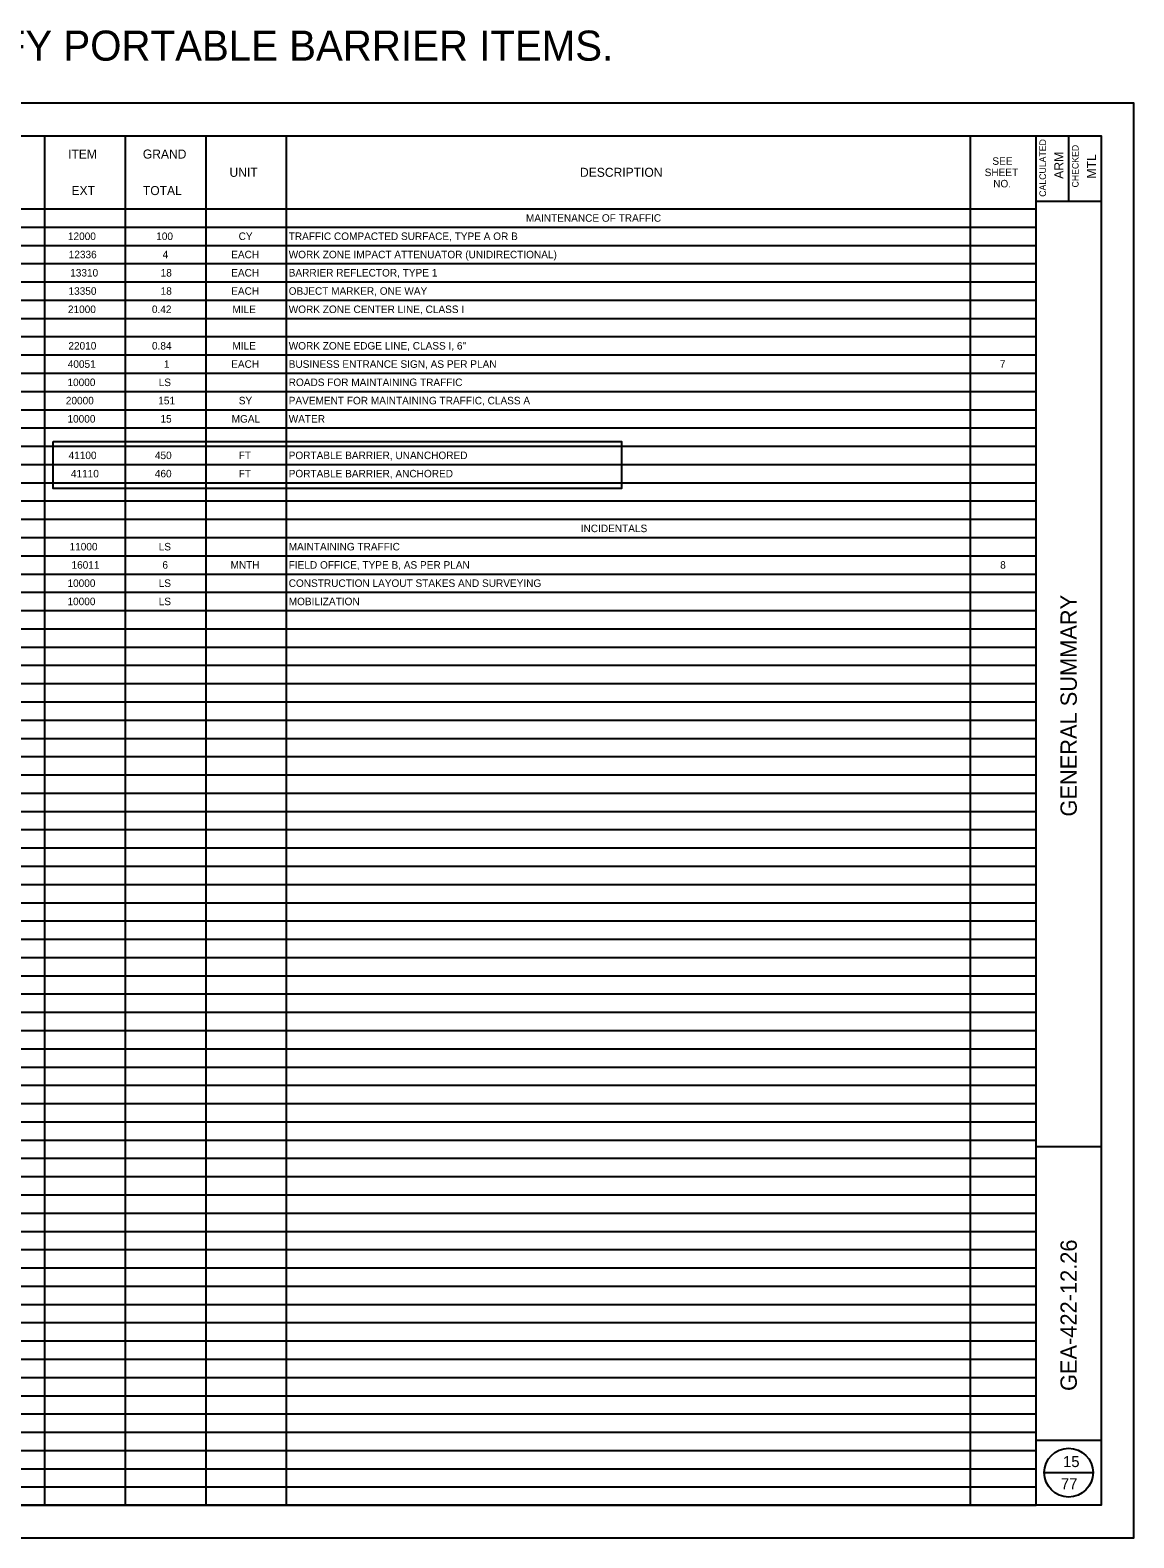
# Model space of a CAD drawing. Extents: x 0 to 34, y 0 to 23.1.
# Drawn here: x 17.07 to 34, y 0 to 23.12 of the extents above; entities that cross this region are included whole.
import ezdxf

# ---------------------------------------------------------------- set-up
doc = ezdxf.new("R2010")
doc.units = 0
for name, color, linetype in [('SC_Scratch1', 7, 'Continuous'), ('SH_Border', 7, 'Continuous'), ('SH_Cut_Line', 7, 'Continuous'), ('SH_Data', 7, 'Continuous'), ('SH_Text', 7, 'Continuous')]:
    doc.layers.add(name, color=color, linetype=linetype)

msp = doc.modelspace()

# ---------------------------------------------------------------- linework, layer by layer
at = {"layer": 'SC_Scratch1'}
msp.add_lwpolyline([(17.425, 16.812), (26.141, 16.812), (26.141, 16.091), (17.425, 16.091)], close=True, dxfattribs=at)
at = {"layer": 'SH_Border'}
for p, q in [((32.5, 0.5), (32.5, 21.5)), ((33, 21.5), (33, 20.5)), ((32.5, 20.5), (33.5, 20.5)), ((32.5, 6), (33.5, 6)), ((32.5, 1.5), (33.5, 1.5))]:
    msp.add_line(p, q, dxfattribs=at)
msp.add_lwpolyline([(2, 21.5), (33.5, 21.5), (33.5, 0.5), (2, 0.5)], close=True, dxfattribs=at)
at = {"layer": 'SH_Cut_Line'}
msp.add_lwpolyline([(0, 0), (34, 0), (34, 22), (0, 22)], close=True, dxfattribs=at)
at = {"layer": 'SH_Data'}
msp.add_line((32.625, 1), (33.375, 1), dxfattribs=at)
msp.add_circle((33, 1), 0.375, dxfattribs=at)
at = {"layer": 'SH_Text'}
for p, q in [((2, 21.5), (32.5, 21.5)), ((17.299, 0.5), (17.299, 21.5)), ((18.535, 0.5), (18.535, 21.5)), ((19.77, 0.5), (19.77, 21.5)), ((21.005, 0.5), (21.005, 21.5)), ((31.495, 0.5), (31.495, 21.5)), ((32.5, 0.5), (32.5, 21.5)), ((14.055, 20.38), (32.5, 20.38)), ((19.77, 20.38), (32.5, 20.38)), ((2, 20.1), (32.5, 20.1)), ((2, 19.82), (32.5, 19.82)), ((2, 19.54), (32.5, 19.54)), ((2, 19.26), (32.5, 19.26)), ((2, 18.98), (32.5, 18.98)), ((2, 18.7), (32.5, 18.7)), ((2, 18.42), (32.5, 18.42)), ((2, 18.14), (32.5, 18.14)), ((2, 17.86), (32.5, 17.86)), ((2, 17.58), (32.5, 17.58)), ((2, 17.3), (32.5, 17.3)), ((2, 17.02), (32.5, 17.02)), ((2, 16.74), (32.5, 16.74)), ((2, 16.46), (32.5, 16.46)), ((2, 16.18), (32.5, 16.18)), ((2, 15.9), (32.5, 15.9)), ((2, 15.62), (32.5, 15.62)), ((2, 15.34), (32.5, 15.34)), ((2, 15.06), (32.5, 15.06)), ((2, 14.78), (32.5, 14.78)), ((2, 14.5), (32.5, 14.5)), ((2, 14.22), (32.5, 14.22)), ((2, 13.94), (32.5, 13.94)), ((2, 13.66), (32.5, 13.66)), ((2, 13.38), (32.5, 13.38)), ((2, 13.1), (32.5, 13.1)), ((2, 12.82), (32.5, 12.82)), ((2, 12.54), (32.5, 12.54)), ((2, 12.26), (32.5, 12.26)), ((2, 11.98), (32.5, 11.98)), ((2, 11.7), (32.5, 11.7)), ((2, 11.42), (32.5, 11.42)), ((2, 11.14), (32.5, 11.14)), ((2, 10.86), (32.5, 10.86)), ((2, 10.58), (32.5, 10.58)), ((2, 10.3), (32.5, 10.3)), ((2, 10.02), (32.5, 10.02)), ((2, 9.74), (32.5, 9.74)), ((2, 9.46), (32.5, 9.46)), ((2, 9.18), (32.5, 9.18)), ((2, 8.9), (32.5, 8.9)), ((2, 8.62), (32.5, 8.62)), ((2, 8.34), (32.5, 8.34)), ((2, 8.06), (32.5, 8.06)), ((2, 7.78), (32.5, 7.78)), ((2, 7.5), (32.5, 7.5)), ((2, 7.22), (32.5, 7.22)), ((2, 6.94), (32.5, 6.94)), ((2, 6.66), (32.5, 6.66)), ((2, 6.38), (32.5, 6.38)), ((2, 6.1), (32.5, 6.1)), ((2, 5.82), (32.5, 5.82)), ((2, 5.54), (32.5, 5.54)), ((2, 5.26), (32.5, 5.26)), ((2, 4.98), (32.5, 4.98)), ((2, 4.7), (32.5, 4.7)), ((2, 4.42), (32.5, 4.42)), ((2, 4.14), (32.5, 4.14)), ((2, 3.86), (32.5, 3.86)), ((2, 3.58), (32.5, 3.58)), ((2, 3.3), (32.5, 3.3)), ((2, 3.02), (32.5, 3.02)), ((2, 2.74), (32.5, 2.74)), ((2, 2.46), (32.5, 2.46)), ((2, 2.18), (32.5, 2.18)), ((2, 1.9), (32.5, 1.9)), ((2, 1.62), (32.5, 1.62)), ((2, 1.34), (32.5, 1.34)), ((2, 1.06), (32.5, 1.06)), ((2, 0.78), (32.5, 0.78)), ((2, 0.5), (32.5, 0.5))]:
    msp.add_line(p, q, dxfattribs=at)

# ---------------------------------------------------------------- texts
at = {"layer": 'SH_Data'}
for s, height, p in [('CALCULATED', 0.1, (32.652, 20.565)), ('CHECKED', 0.1, (33.152, 20.708)), ('ARM', 0.14, (32.92, 20.84)), ('MTL', 0.14, (33.42, 20.844)), ('GENERAL SUMMARY', 0.25, (33.125, 11.061)), ('GEA-422-12.26', 0.25, (33.125, 2.252))]:
    msp.add_text(s, height=height, rotation=90, dxfattribs=at).set_placement(p)
for s, p in [('15', (32.914, 1.085)), ('77', (32.882, 0.745))]:
    msp.add_text(s, height=0.17, dxfattribs=at).set_placement(p)
at = {"layer": 'SH_Text'}
for s, height, p in [('SPREADSHEET UNLINKED TO MODIFY PORTABLE BARRIER ITEMS.', 0.46136, (5.927, 22.652)), ('ITEM', 0.1384, (17.654, 21.151)), ('GRAND', 0.1384, (18.801, 21.151)), ('SEE', 0.1153, (31.83, 21.055)), ('UNIT', 0.1384, (20.13, 20.871)), ('DESCRIPTION', 0.13841, (25.506, 20.871)), ('SHEET', 0.1153, (31.712, 20.882)), ('NO.', 0.1153, (31.843, 20.709)), ('EXT', 0.1384, (17.707, 20.591)), ('TOTAL', 0.1384, (18.802, 20.591)), ('MAINTENANCE OF TRAFFIC', 0.11534, (24.676, 20.182)), ('12000', 0.1153, (17.652, 19.902)), ('100', 0.1153, (19.006, 19.902)), ('CY', 0.1153, (20.27, 19.902)), ('TRAFFIC COMPACTED SURFACE, TYPE A OR B ', 0.11534, (21.038, 19.902)), ('12336', 0.1153, (17.664, 19.622)), ('4', 0.115, (19.104, 19.622)), ('EACH', 0.1153, (20.156, 19.622)), ('WORK ZONE IMPACT ATTENUATOR (UNIDIRECTIONAL) ', 0.11534, (21.038, 19.622)), ('13310', 0.1153, (17.687, 19.342)), ('18', 0.1153, (19.074, 19.342)), ('EACH', 0.1153, (20.156, 19.342)), ('BARRIER REFLECTOR, TYPE 1 ', 0.11534, (21.038, 19.342)), ('13350', 0.1153, (17.661, 19.062)), ('18', 0.1153, (19.074, 19.062)), ('EACH', 0.1153, (20.156, 19.062)), ('OBJECT MARKER, ONE WAY ', 0.11534, (21.038, 19.062)), ('21000', 0.1153, (17.652, 18.782)), ('0.42', 0.1153, (18.94, 18.782)), ('MILE', 0.1153, (20.174, 18.782)), ('WORK ZONE CENTER LINE, CLASS I ', 0.11534, (21.038, 18.782)), ('22010', 0.1153, (17.659, 18.222)), ('0.84', 0.1153, (18.941, 18.222)), ('MILE', 0.1153, (20.174, 18.222)), ('WORK ZONE EDGE LINE, CLASS I, 6" ', 0.11534, (21.038, 18.222)), ('40051', 0.1153, (17.649, 17.942)), ('1', 0.115, (19.125, 17.942)), ('EACH', 0.1153, (20.156, 17.942)), ('BUSINESS ENTRANCE SIGN, AS PER PLAN ', 0.11534, (21.038, 17.942)), ('7', 0.115, (31.944, 17.942)), ('10000', 0.1153, (17.645, 17.662)), ('LS', 0.1153, (19.044, 17.662)), ('ROADS FOR MAINTAINING TRAFFIC', 0.11534, (21.038, 17.662)), ('20000', 0.1153, (17.62, 17.382)), ('151', 0.1153, (19.037, 17.382)), ('SY', 0.1153, (20.272, 17.382)), ('PAVEMENT FOR MAINTAINING TRAFFIC, CLASS A ', 0.11534, (21.038, 17.382)), ('10000', 0.1153, (17.645, 17.102)), ('15', 0.1153, (19.071, 17.102)), ('MGAL', 0.1153, (20.163, 17.102)), ('WATER ', 0.1153, (21.038, 17.102)), ('41100', 0.1153, (17.662, 16.542)), ('450', 0.1153, (18.986, 16.542)), ('FT', 0.1153, (20.272, 16.542)), ('PORTABLE BARRIER, UNANCHORED', 0.11534, (21.038, 16.542)), ('41110', 0.1153, (17.698, 16.262)), ('460', 0.1153, (18.985, 16.262)), ('FT', 0.1153, (20.272, 16.262)), ('PORTABLE BARRIER, ANCHORED', 0.11534, (21.038, 16.262)), ('INCIDENTALS', 0.11534, (25.517, 15.422)), ('11000', 0.1153, (17.677, 15.142)), ('LS', 0.1153, (19.044, 15.142)), ('MAINTAINING TRAFFIC', 0.11534, (21.038, 15.142)), ('16011', 0.1153, (17.707, 14.862)), ('6', 0.115, (19.101, 14.862)), ('MNTH', 0.1153, (20.146, 14.862)), ('FIELD OFFICE, TYPE B, AS PER PLAN', 0.11534, (21.038, 14.862)), ('8', 0.115, (31.95, 14.862)), ('10000', 0.1153, (17.645, 14.582)), ('LS', 0.1153, (19.044, 14.582)), ('CONSTRUCTION LAYOUT STAKES AND SURVEYING', 0.11534, (21.038, 14.582)), ('10000', 0.1153, (17.645, 14.302)), ('LS', 0.1153, (19.044, 14.302)), ('MOBILIZATION', 0.11534, (21.038, 14.302))]:
    msp.add_text(s, height=height, dxfattribs=at).set_placement(p)

doc.saveas('drawing.dxf')
